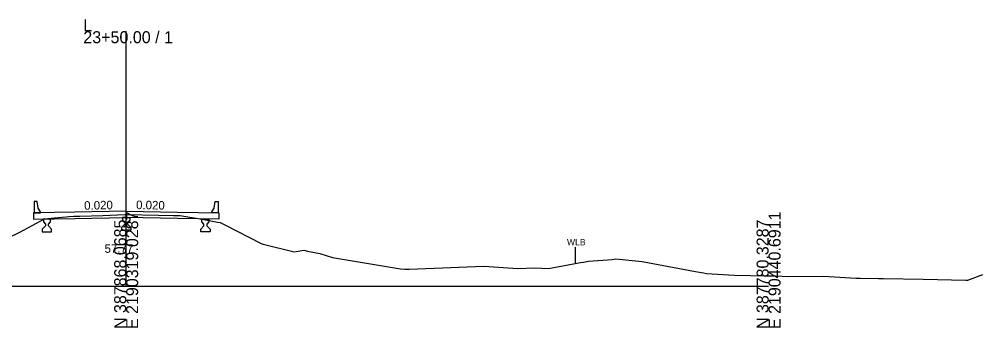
# Model space of a CAD drawing. Extents: x -26 to 2190750, y -10 to 388496.
# Drawn here: x 175 to 400, y 7490.3 to 7562.4 of the extents above; entities that cross this region are included whole.
import ezdxf

# ---------------------------------------------------------------- set-up
doc = ezdxf.new("R2010")
doc.units = 0
for name, color, linetype in [('Exist Cross Section Cell', 7, 'Continuous'), ('Exist XS Center Line Elevation Label', 7, 'Continuous'), ('Exist XS Ground Line', 7, 'Continuous'), ('Prop CMT Concrete Structures', 7, 'Continuous'), ('Prop RDY Alternate Text Blue', 7, 'Continuous'), ('Prop XS SE Text', 7, 'Continuous')]:
    doc.layers.add(name, color=color, linetype=linetype)

msp = doc.modelspace()

# ---------------------------------------------------------------- linework, layer by layer
at = {"layer": 'Exist Cross Section Cell'}
for p, q in [((200, 7500), (200, 7559.64)), ((50, 7500), (200, 7500)), ((200, 7500), (350, 7500))]:
    msp.add_line(p, q, dxfattribs=at)
at = {"layer": 'Exist XS Ground Line'}
msp.add_lwpolyline([(172.48, 7511.33), (175.15, 7512.66), (180.95, 7515.78), (183.28, 7516), (186.02, 7516.27), (186.64, 7516.35), (187.79, 7516.38), (189.15, 7516.41), (194.54, 7516.59), (199.66, 7516.78), (200, 7516.77), (207.55, 7516.62), (211.07, 7516.56), (211.49, 7516.56), (212.5, 7516.57), (217.78, 7515.68), (221.34, 7515.02), (221.98, 7514.9), (223, 7514.36), (231.49, 7510.01), (231.99, 7509.84), (239.21, 7508.05), (241.51, 7508.42), (242.31, 7508.18), (245.2, 7507.66), (248.19, 7506.75), (264.03, 7504.06), (265.08, 7504.03), (266.06, 7504), (283.55, 7504.71), (291.44, 7504.16), (295.23, 7504.35), (297.03, 7504.22), (298.62, 7504.14), (306.09, 7505.54), (306.77, 7505.66), (307.96, 7505.89), (313.48, 7506.23), (314.33, 7506.45), (320.5, 7505.77), (332.91, 7503.47), (334.81, 7503.14), (335.52, 7502.96), (341.96, 7502.57), (349.53, 7502.47), (350.43, 7502.46), (351.63, 7502.42), (354.72, 7502.31), (362.91, 7502.39), (370.34, 7501.87), (371.36, 7501.87), (375.69, 7501.85), (376.86, 7501.83), (386.1, 7501.68), (396.03, 7501.43), (396.55, 7501.42), (400, 7502.75)], dxfattribs=at)
at = {"layer": 'Prop CMT Concrete Structures'}
for points in [[(180, 7517.19), (180, 7517.44), (179.42, 7518.24), (179.25, 7519.83), (178.5, 7519.83), (178.5, 7517.16)], [(220, 7517.19), (220, 7517.44), (220.58, 7518.24), (220.75, 7519.83), (221.5, 7519.83), (221.5, 7517.16)], [(200, 7517.59), (188, 7517.35), (178.37, 7517.16)], [(178.37, 7517.16), (178.37, 7515.66)], [(178.37, 7515.66), (188, 7515.85), (200, 7516.09)], [(178.5, 7517.16), (180, 7517.19)], [(200, 7516.09), (199.17, 7516.07)], [(199.17, 7516.07), (199.17, 7515.42)], [(200, 7516.09), (200, 7517.59)], [(200, 7517.59), (212, 7517.35), (221.62, 7517.16)], [(221.62, 7515.66), (212, 7515.85), (200, 7516.09)], [(200, 7516.09), (200.83, 7516.07)], [(200.83, 7516.07), (200.83, 7515.42)], [(221.5, 7517.16), (220, 7517.19)], [(221.62, 7517.16), (221.62, 7515.66)], [(181.17, 7514.14), (180.42, 7513.39)], [(182.33, 7515.74), (181.5, 7515.72), (180.67, 7515.7)], [(180.67, 7515.7), (180.67, 7515.05)], [(180.67, 7515.05), (181.17, 7514.55)], [(181.17, 7514.55), (181.17, 7514.14)], [(181.83, 7514.55), (182.33, 7515.05)], [(181.83, 7514.14), (181.83, 7514.55)], [(182.58, 7513.39), (181.83, 7514.14)], [(182.33, 7515.05), (182.33, 7515.74)], [(199.67, 7514.51), (198.92, 7513.76)], [(198.92, 7513.76), (198.92, 7513.09)], [(199.17, 7515.42), (199.67, 7514.92)], [(199.67, 7514.92), (199.67, 7514.51)], [(200.83, 7515.42), (200.33, 7514.92)], [(200.33, 7514.92), (200.33, 7514.51)], [(200.33, 7514.51), (201.08, 7513.76)], [(201.08, 7513.76), (201.08, 7513.09)], [(217.42, 7513.39), (218.17, 7514.14)], [(217.67, 7515.74), (218.5, 7515.72), (219.33, 7515.7)], [(217.67, 7515.05), (217.67, 7515.74)], [(218.17, 7514.55), (217.67, 7515.05)], [(218.17, 7514.14), (218.17, 7514.55)], [(219.33, 7515.05), (218.83, 7514.55)], [(218.83, 7514.55), (218.83, 7514.14)], [(218.83, 7514.14), (219.58, 7513.39)], [(219.33, 7515.7), (219.33, 7515.05)], [(180.42, 7513.39), (180.42, 7512.72)], [(180.42, 7512.72), (181.5, 7512.72), (182.58, 7512.72)], [(182.58, 7512.72), (182.58, 7513.39)], [(198.92, 7513.09), (200, 7513.09)], [(201.08, 7513.09), (200, 7513.09)], [(217.42, 7512.72), (217.42, 7513.39)], [(219.58, 7512.72), (218.5, 7512.72), (217.42, 7512.72)], [(219.58, 7513.39), (219.58, 7512.72)]]:
    msp.add_lwpolyline(points, dxfattribs=at)
at = {"layer": 'Prop RDY Alternate Text Blue'}
msp.add_line((304.84, 7509.13), (304.84, 7505.31), dxfattribs=at)

# ---------------------------------------------------------------- texts
at = {"layer": 'Exist Cross Section Cell'}
for s, p in [('L', (190, 7559.64)), ('23+50.00 / 1', (190, 7556.84))]:
    msp.add_text(s, height=2.8, dxfattribs=at).set_placement(p)
for s, p in [('E 2190319.0287', (202.8, 7490)), ('E 2190440.6911', (352.8, 7490)), ('N 387868.0685', (200, 7490)), ('N 387780.3287', (350, 7490))]:
    msp.add_text(s, height=2.8, rotation=90, dxfattribs=at).set_placement(p)
at = {"layer": 'Exist XS Center Line Elevation Label'}
msp.add_text('57.77', height=2, dxfattribs=at).set_placement((194.96, 7507.83))
at = {"layer": 'Prop RDY Alternate Text Blue'}
msp.add_text('WLB', height=1.5, dxfattribs=at).set_placement((302.92, 7509.59))
at = {"layer": 'Prop XS SE Text'}
for rotation, p in [(1.1458, (190.21, 7517.89)), (358.8542, (202.3, 7518.05))]:
    msp.add_text('0.020', height=2, rotation=rotation, dxfattribs=at).set_placement(p)

doc.saveas('drawing.dxf')
